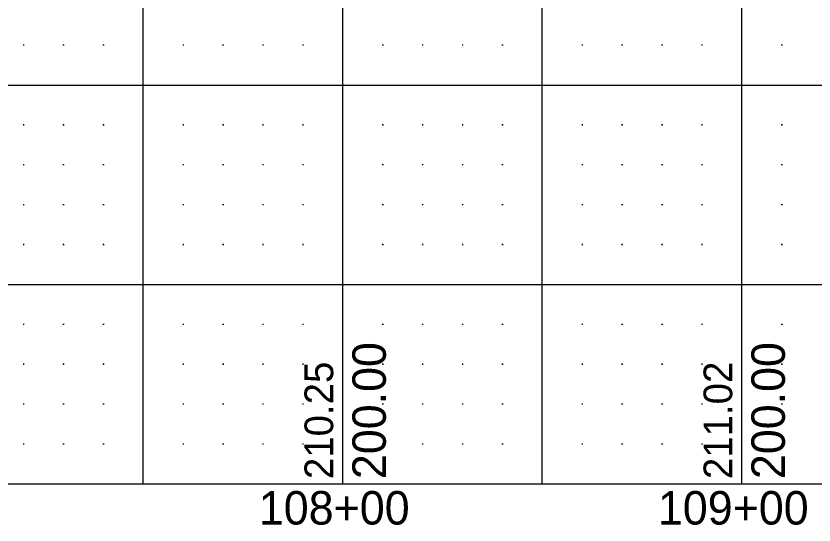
# Model space of a CAD drawing. Extents: x 471 to 2121, y 140 to 650.
# Drawn here: x 1354.2 to 1554.2, y 139.7 to 267.3 of the extents above; entities that cross this region are included whole.
import ezdxf

# ---------------------------------------------------------------- set-up
doc = ezdxf.new("R2010")
doc.units = 0
for name, color, linetype in [('DSN_DRFT_Border Grid', 7, 'Continuous'), ('DSN_RDWY_Prof Annotation', 7, 'Continuous'), ('EX_Profile Annotation', 7, 'Continuous')]:
    doc.layers.add(name, color=color, linetype=linetype)

msp = doc.modelspace()

# ---------------------------------------------------------------- linework, layer by layer
at = {"layer": 'DSN_DRFT_Border Grid'}
for p, q in [((1386.06, 150), (1386.06, 650)), ((1386.06, 150), (1386.06, 650)), ((1436.06, 150), (1436.06, 650)), ((1436.06, 150), (1436.06, 650)), ((1486.06, 150), (1486.06, 650)), ((1486.06, 150), (1486.06, 650)), ((1536.06, 150), (1536.06, 650)), ((1536.06, 150), (1536.06, 650)), ((1356.06, 260.12), (1356.06, 259.88)), ((1356.06, 260.12), (1356.06, 259.88)), ((1366.06, 260.12), (1366.06, 259.88)), ((1366.06, 260.12), (1366.06, 259.88)), ((1376.06, 260.12), (1376.06, 259.88)), ((1376.06, 260.12), (1376.06, 259.88)), ((1396.06, 260.12), (1396.06, 259.88)), ((1396.06, 260.12), (1396.06, 259.88)), ((1406.06, 260.12), (1406.06, 259.88)), ((1406.06, 260.12), (1406.06, 259.88)), ((1416.06, 260.12), (1416.06, 259.88)), ((1416.06, 260.12), (1416.06, 259.88)), ((1426.06, 260.12), (1426.06, 259.88)), ((1426.06, 260.12), (1426.06, 259.88)), ((1446.06, 260.12), (1446.06, 259.88)), ((1446.06, 260.12), (1446.06, 259.88)), ((1456.06, 260.12), (1456.06, 259.88)), ((1456.06, 260.12), (1456.06, 259.88)), ((1466.06, 260.12), (1466.06, 259.88)), ((1466.06, 260.12), (1466.06, 259.88)), ((1476.06, 260.12), (1476.06, 259.88)), ((1476.06, 260.12), (1476.06, 259.88)), ((1496.06, 260.12), (1496.06, 259.88)), ((1496.06, 260.12), (1496.06, 259.88)), ((1506.06, 260.12), (1506.06, 259.88)), ((1506.06, 260.12), (1506.06, 259.88)), ((1516.06, 260.12), (1516.06, 259.88)), ((1516.06, 260.12), (1516.06, 259.88)), ((1526.06, 260.12), (1526.06, 259.88)), ((1526.06, 260.12), (1526.06, 259.88)), ((1546.06, 260.12), (1546.06, 259.88)), ((1546.06, 260.12), (1546.06, 259.88)), ((1356.18, 260), (1355.94, 260)), ((1356.18, 260), (1355.94, 260)), ((1366.18, 260), (1365.94, 260)), ((1366.18, 260), (1365.94, 260)), ((1376.18, 260), (1375.94, 260)), ((1376.18, 260), (1375.94, 260)), ((1396.18, 260), (1395.94, 260)), ((1396.18, 260), (1395.94, 260)), ((1406.18, 260), (1405.94, 260)), ((1406.18, 260), (1405.94, 260)), ((1416.18, 260), (1415.94, 260)), ((1416.18, 260), (1415.94, 260)), ((1426.18, 260), (1425.94, 260)), ((1426.18, 260), (1425.94, 260)), ((1446.18, 260), (1445.94, 260)), ((1446.18, 260), (1445.94, 260)), ((1456.18, 260), (1455.94, 260)), ((1456.18, 260), (1455.94, 260)), ((1466.18, 260), (1465.94, 260)), ((1466.18, 260), (1465.94, 260)), ((1476.18, 260), (1475.94, 260)), ((1476.18, 260), (1475.94, 260)), ((1496.18, 260), (1495.94, 260)), ((1496.18, 260), (1495.94, 260)), ((1506.18, 260), (1505.94, 260)), ((1506.18, 260), (1505.94, 260)), ((1516.18, 260), (1515.94, 260)), ((1516.18, 260), (1515.94, 260)), ((1526.18, 260), (1525.94, 260)), ((1526.18, 260), (1525.94, 260)), ((1546.18, 260), (1545.94, 260)), ((1546.18, 260), (1545.94, 260)), ((521.06, 250), (2071.06, 250)), ((521.06, 250), (2071.06, 250)), ((1356.06, 240.12), (1356.06, 239.88)), ((1356.06, 240.12), (1356.06, 239.88)), ((1366.06, 240.12), (1366.06, 239.88)), ((1366.06, 240.12), (1366.06, 239.88)), ((1376.06, 240.12), (1376.06, 239.88)), ((1376.06, 240.12), (1376.06, 239.88)), ((1396.06, 240.12), (1396.06, 239.88)), ((1396.06, 240.12), (1396.06, 239.88)), ((1406.06, 240.12), (1406.06, 239.88)), ((1406.06, 240.12), (1406.06, 239.88)), ((1416.06, 240.12), (1416.06, 239.88)), ((1416.06, 240.12), (1416.06, 239.88)), ((1426.06, 240.12), (1426.06, 239.88)), ((1426.06, 240.12), (1426.06, 239.88)), ((1446.06, 240.12), (1446.06, 239.88)), ((1446.06, 240.12), (1446.06, 239.88)), ((1456.06, 240.12), (1456.06, 239.88)), ((1456.06, 240.12), (1456.06, 239.88)), ((1466.06, 240.12), (1466.06, 239.88)), ((1466.06, 240.12), (1466.06, 239.88)), ((1476.06, 240.12), (1476.06, 239.88)), ((1476.06, 240.12), (1476.06, 239.88)), ((1496.06, 240.12), (1496.06, 239.88)), ((1496.06, 240.12), (1496.06, 239.88)), ((1506.06, 240.12), (1506.06, 239.88)), ((1506.06, 240.12), (1506.06, 239.88)), ((1516.06, 240.12), (1516.06, 239.88)), ((1516.06, 240.12), (1516.06, 239.88)), ((1526.06, 240.12), (1526.06, 239.88)), ((1526.06, 240.12), (1526.06, 239.88)), ((1546.06, 240.12), (1546.06, 239.88)), ((1546.06, 240.12), (1546.06, 239.88)), ((1356.18, 240), (1355.94, 240)), ((1356.18, 240), (1355.94, 240)), ((1366.18, 240), (1365.94, 240)), ((1366.18, 240), (1365.94, 240)), ((1376.18, 240), (1375.94, 240)), ((1376.18, 240), (1375.94, 240)), ((1396.18, 240), (1395.94, 240)), ((1396.18, 240), (1395.94, 240)), ((1406.18, 240), (1405.94, 240)), ((1406.18, 240), (1405.94, 240)), ((1416.18, 240), (1415.94, 240)), ((1416.18, 240), (1415.94, 240)), ((1426.18, 240), (1425.94, 240)), ((1426.18, 240), (1425.94, 240)), ((1446.18, 240), (1445.94, 240)), ((1446.18, 240), (1445.94, 240)), ((1456.18, 240), (1455.94, 240)), ((1456.18, 240), (1455.94, 240)), ((1466.18, 240), (1465.94, 240)), ((1466.18, 240), (1465.94, 240)), ((1476.18, 240), (1475.94, 240)), ((1476.18, 240), (1475.94, 240)), ((1496.18, 240), (1495.94, 240)), ((1496.18, 240), (1495.94, 240)), ((1506.18, 240), (1505.94, 240)), ((1506.18, 240), (1505.94, 240)), ((1516.18, 240), (1515.94, 240)), ((1516.18, 240), (1515.94, 240)), ((1526.18, 240), (1525.94, 240)), ((1526.18, 240), (1525.94, 240)), ((1546.18, 240), (1545.94, 240)), ((1546.18, 240), (1545.94, 240)), ((1356.06, 230.12), (1356.06, 229.88)), ((1356.06, 230.12), (1356.06, 229.88)), ((1366.06, 230.12), (1366.06, 229.88)), ((1366.06, 230.12), (1366.06, 229.88)), ((1376.06, 230.12), (1376.06, 229.88)), ((1376.06, 230.12), (1376.06, 229.88)), ((1396.06, 230.12), (1396.06, 229.88)), ((1396.06, 230.12), (1396.06, 229.88)), ((1406.06, 230.12), (1406.06, 229.88)), ((1406.06, 230.12), (1406.06, 229.88)), ((1416.06, 230.12), (1416.06, 229.88)), ((1416.06, 230.12), (1416.06, 229.88)), ((1426.06, 230.12), (1426.06, 229.88)), ((1426.06, 230.12), (1426.06, 229.88)), ((1446.06, 230.12), (1446.06, 229.88)), ((1446.06, 230.12), (1446.06, 229.88)), ((1456.06, 230.12), (1456.06, 229.88)), ((1456.06, 230.12), (1456.06, 229.88)), ((1466.06, 230.12), (1466.06, 229.88)), ((1466.06, 230.12), (1466.06, 229.88)), ((1476.06, 230.12), (1476.06, 229.88)), ((1476.06, 230.12), (1476.06, 229.88)), ((1496.06, 230.12), (1496.06, 229.88)), ((1496.06, 230.12), (1496.06, 229.88)), ((1506.06, 230.12), (1506.06, 229.88)), ((1506.06, 230.12), (1506.06, 229.88)), ((1516.06, 230.12), (1516.06, 229.88)), ((1516.06, 230.12), (1516.06, 229.88)), ((1526.06, 230.12), (1526.06, 229.88)), ((1526.06, 230.12), (1526.06, 229.88)), ((1546.06, 230.12), (1546.06, 229.88)), ((1546.06, 230.12), (1546.06, 229.88)), ((1356.18, 230), (1355.94, 230)), ((1356.18, 230), (1355.94, 230)), ((1366.18, 230), (1365.94, 230)), ((1366.18, 230), (1365.94, 230)), ((1376.18, 230), (1375.94, 230)), ((1376.18, 230), (1375.94, 230)), ((1396.18, 230), (1395.94, 230)), ((1396.18, 230), (1395.94, 230)), ((1406.18, 230), (1405.94, 230)), ((1406.18, 230), (1405.94, 230)), ((1416.18, 230), (1415.94, 230)), ((1416.18, 230), (1415.94, 230)), ((1426.18, 230), (1425.94, 230)), ((1426.18, 230), (1425.94, 230)), ((1446.18, 230), (1445.94, 230)), ((1446.18, 230), (1445.94, 230)), ((1456.18, 230), (1455.94, 230)), ((1456.18, 230), (1455.94, 230)), ((1466.18, 230), (1465.94, 230)), ((1466.18, 230), (1465.94, 230)), ((1476.18, 230), (1475.94, 230)), ((1476.18, 230), (1475.94, 230)), ((1496.18, 230), (1495.94, 230)), ((1496.18, 230), (1495.94, 230)), ((1506.18, 230), (1505.94, 230)), ((1506.18, 230), (1505.94, 230)), ((1516.18, 230), (1515.94, 230)), ((1516.18, 230), (1515.94, 230)), ((1526.18, 230), (1525.94, 230)), ((1526.18, 230), (1525.94, 230)), ((1546.18, 230), (1545.94, 230)), ((1546.18, 230), (1545.94, 230)), ((1356.06, 220.12), (1356.06, 219.88)), ((1356.06, 220.12), (1356.06, 219.88)), ((1366.06, 220.12), (1366.06, 219.88)), ((1366.06, 220.12), (1366.06, 219.88)), ((1376.06, 220.12), (1376.06, 219.88)), ((1376.06, 220.12), (1376.06, 219.88)), ((1396.06, 220.12), (1396.06, 219.88)), ((1396.06, 220.12), (1396.06, 219.88)), ((1406.06, 220.12), (1406.06, 219.88)), ((1406.06, 220.12), (1406.06, 219.88)), ((1416.06, 220.12), (1416.06, 219.88)), ((1416.06, 220.12), (1416.06, 219.88)), ((1426.06, 220.12), (1426.06, 219.88)), ((1426.06, 220.12), (1426.06, 219.88)), ((1446.06, 220.12), (1446.06, 219.88)), ((1446.06, 220.12), (1446.06, 219.88)), ((1456.06, 220.12), (1456.06, 219.88)), ((1456.06, 220.12), (1456.06, 219.88)), ((1466.06, 220.12), (1466.06, 219.88)), ((1466.06, 220.12), (1466.06, 219.88)), ((1476.06, 220.12), (1476.06, 219.88)), ((1476.06, 220.12), (1476.06, 219.88)), ((1496.06, 220.12), (1496.06, 219.88)), ((1496.06, 220.12), (1496.06, 219.88)), ((1506.06, 220.12), (1506.06, 219.88)), ((1506.06, 220.12), (1506.06, 219.88)), ((1516.06, 220.12), (1516.06, 219.88)), ((1516.06, 220.12), (1516.06, 219.88)), ((1526.06, 220.12), (1526.06, 219.88)), ((1526.06, 220.12), (1526.06, 219.88)), ((1546.06, 220.12), (1546.06, 219.88)), ((1546.06, 220.12), (1546.06, 219.88)), ((1356.18, 220), (1355.94, 220)), ((1356.18, 220), (1355.94, 220)), ((1366.18, 220), (1365.94, 220)), ((1366.18, 220), (1365.94, 220)), ((1376.18, 220), (1375.94, 220)), ((1376.18, 220), (1375.94, 220)), ((1396.18, 220), (1395.94, 220)), ((1396.18, 220), (1395.94, 220)), ((1406.18, 220), (1405.94, 220)), ((1406.18, 220), (1405.94, 220)), ((1416.18, 220), (1415.94, 220)), ((1416.18, 220), (1415.94, 220)), ((1426.18, 220), (1425.94, 220)), ((1426.18, 220), (1425.94, 220)), ((1446.18, 220), (1445.94, 220)), ((1446.18, 220), (1445.94, 220)), ((1456.18, 220), (1455.94, 220)), ((1456.18, 220), (1455.94, 220)), ((1466.18, 220), (1465.94, 220)), ((1466.18, 220), (1465.94, 220)), ((1476.18, 220), (1475.94, 220)), ((1476.18, 220), (1475.94, 220)), ((1496.18, 220), (1495.94, 220)), ((1496.18, 220), (1495.94, 220)), ((1506.18, 220), (1505.94, 220)), ((1506.18, 220), (1505.94, 220)), ((1516.18, 220), (1515.94, 220)), ((1516.18, 220), (1515.94, 220)), ((1526.18, 220), (1525.94, 220)), ((1526.18, 220), (1525.94, 220)), ((1546.18, 220), (1545.94, 220)), ((1546.18, 220), (1545.94, 220)), ((1356.06, 210.12), (1356.06, 209.88)), ((1356.06, 210.12), (1356.06, 209.88)), ((1366.06, 210.12), (1366.06, 209.88)), ((1366.06, 210.12), (1366.06, 209.88)), ((1376.06, 210.12), (1376.06, 209.88)), ((1376.06, 210.12), (1376.06, 209.88)), ((1396.06, 210.12), (1396.06, 209.88)), ((1396.06, 210.12), (1396.06, 209.88)), ((1406.06, 210.12), (1406.06, 209.88)), ((1406.06, 210.12), (1406.06, 209.88)), ((1416.06, 210.12), (1416.06, 209.88)), ((1416.06, 210.12), (1416.06, 209.88)), ((1426.06, 210.12), (1426.06, 209.88)), ((1426.06, 210.12), (1426.06, 209.88)), ((1446.06, 210.12), (1446.06, 209.88)), ((1446.06, 210.12), (1446.06, 209.88)), ((1456.06, 210.12), (1456.06, 209.88)), ((1456.06, 210.12), (1456.06, 209.88)), ((1466.06, 210.12), (1466.06, 209.88)), ((1466.06, 210.12), (1466.06, 209.88)), ((1476.06, 210.12), (1476.06, 209.88)), ((1476.06, 210.12), (1476.06, 209.88)), ((1496.06, 210.12), (1496.06, 209.88)), ((1496.06, 210.12), (1496.06, 209.88)), ((1506.06, 210.12), (1506.06, 209.88)), ((1506.06, 210.12), (1506.06, 209.88)), ((1516.06, 210.12), (1516.06, 209.88)), ((1516.06, 210.12), (1516.06, 209.88)), ((1526.06, 210.12), (1526.06, 209.88)), ((1526.06, 210.12), (1526.06, 209.88)), ((1546.06, 210.12), (1546.06, 209.88)), ((1546.06, 210.12), (1546.06, 209.88)), ((1356.18, 210), (1355.94, 210)), ((1356.18, 210), (1355.94, 210)), ((1366.18, 210), (1365.94, 210)), ((1366.18, 210), (1365.94, 210)), ((1376.18, 210), (1375.94, 210)), ((1376.18, 210), (1375.94, 210)), ((1396.18, 210), (1395.94, 210)), ((1396.18, 210), (1395.94, 210)), ((1406.18, 210), (1405.94, 210)), ((1406.18, 210), (1405.94, 210)), ((1416.18, 210), (1415.94, 210)), ((1416.18, 210), (1415.94, 210)), ((1426.18, 210), (1425.94, 210)), ((1426.18, 210), (1425.94, 210)), ((1446.18, 210), (1445.94, 210)), ((1446.18, 210), (1445.94, 210)), ((1456.18, 210), (1455.94, 210)), ((1456.18, 210), (1455.94, 210)), ((1466.18, 210), (1465.94, 210)), ((1466.18, 210), (1465.94, 210)), ((1476.18, 210), (1475.94, 210)), ((1476.18, 210), (1475.94, 210)), ((1496.18, 210), (1495.94, 210)), ((1496.18, 210), (1495.94, 210)), ((1506.18, 210), (1505.94, 210)), ((1506.18, 210), (1505.94, 210)), ((1516.18, 210), (1515.94, 210)), ((1516.18, 210), (1515.94, 210)), ((1526.18, 210), (1525.94, 210)), ((1526.18, 210), (1525.94, 210)), ((1546.18, 210), (1545.94, 210)), ((1546.18, 210), (1545.94, 210)), ((521.06, 200), (2071.06, 200)), ((521.06, 200), (2071.06, 200)), ((1356.06, 190.12), (1356.06, 189.88)), ((1356.06, 190.12), (1356.06, 189.88)), ((1366.06, 190.12), (1366.06, 189.88)), ((1366.06, 190.12), (1366.06, 189.88)), ((1376.06, 190.12), (1376.06, 189.88)), ((1376.06, 190.12), (1376.06, 189.88)), ((1396.06, 190.12), (1396.06, 189.88)), ((1396.06, 190.12), (1396.06, 189.88)), ((1406.06, 190.12), (1406.06, 189.88)), ((1406.06, 190.12), (1406.06, 189.88)), ((1416.06, 190.12), (1416.06, 189.88)), ((1416.06, 190.12), (1416.06, 189.88)), ((1426.06, 190.12), (1426.06, 189.88)), ((1426.06, 190.12), (1426.06, 189.88)), ((1446.06, 190.12), (1446.06, 189.88)), ((1446.06, 190.12), (1446.06, 189.88)), ((1456.06, 190.12), (1456.06, 189.88)), ((1456.06, 190.12), (1456.06, 189.88)), ((1466.06, 190.12), (1466.06, 189.88)), ((1466.06, 190.12), (1466.06, 189.88)), ((1476.06, 190.12), (1476.06, 189.88)), ((1476.06, 190.12), (1476.06, 189.88)), ((1496.06, 190.12), (1496.06, 189.88)), ((1496.06, 190.12), (1496.06, 189.88)), ((1506.06, 190.12), (1506.06, 189.88)), ((1506.06, 190.12), (1506.06, 189.88)), ((1516.06, 190.12), (1516.06, 189.88)), ((1516.06, 190.12), (1516.06, 189.88)), ((1526.06, 190.12), (1526.06, 189.88)), ((1526.06, 190.12), (1526.06, 189.88)), ((1546.06, 190.12), (1546.06, 189.88)), ((1546.06, 190.12), (1546.06, 189.88)), ((1356.18, 190), (1355.94, 190)), ((1356.18, 190), (1355.94, 190)), ((1366.18, 190), (1365.94, 190)), ((1366.18, 190), (1365.94, 190)), ((1376.18, 190), (1375.94, 190)), ((1376.18, 190), (1375.94, 190)), ((1396.18, 190), (1395.94, 190)), ((1396.18, 190), (1395.94, 190)), ((1406.18, 190), (1405.94, 190)), ((1406.18, 190), (1405.94, 190)), ((1416.18, 190), (1415.94, 190)), ((1416.18, 190), (1415.94, 190)), ((1426.18, 190), (1425.94, 190)), ((1426.18, 190), (1425.94, 190)), ((1446.18, 190), (1445.94, 190)), ((1446.18, 190), (1445.94, 190)), ((1456.18, 190), (1455.94, 190)), ((1456.18, 190), (1455.94, 190)), ((1466.18, 190), (1465.94, 190)), ((1466.18, 190), (1465.94, 190)), ((1476.18, 190), (1475.94, 190)), ((1476.18, 190), (1475.94, 190)), ((1496.18, 190), (1495.94, 190)), ((1496.18, 190), (1495.94, 190)), ((1506.18, 190), (1505.94, 190)), ((1506.18, 190), (1505.94, 190)), ((1516.18, 190), (1515.94, 190)), ((1516.18, 190), (1515.94, 190)), ((1526.18, 190), (1525.94, 190)), ((1526.18, 190), (1525.94, 190)), ((1546.18, 190), (1545.94, 190)), ((1546.18, 190), (1545.94, 190)), ((1356.06, 180.12), (1356.06, 179.88)), ((1356.06, 180.12), (1356.06, 179.88)), ((1366.06, 180.12), (1366.06, 179.88)), ((1366.06, 180.12), (1366.06, 179.88)), ((1376.06, 180.12), (1376.06, 179.88)), ((1376.06, 180.12), (1376.06, 179.88)), ((1396.06, 180.12), (1396.06, 179.88)), ((1396.06, 180.12), (1396.06, 179.88)), ((1406.06, 180.12), (1406.06, 179.88)), ((1406.06, 180.12), (1406.06, 179.88)), ((1416.06, 180.12), (1416.06, 179.88)), ((1416.06, 180.12), (1416.06, 179.88)), ((1426.06, 180.12), (1426.06, 179.88)), ((1426.06, 180.12), (1426.06, 179.88)), ((1446.06, 180.12), (1446.06, 179.88)), ((1446.06, 180.12), (1446.06, 179.88)), ((1456.06, 180.12), (1456.06, 179.88)), ((1456.06, 180.12), (1456.06, 179.88)), ((1466.06, 180.12), (1466.06, 179.88)), ((1466.06, 180.12), (1466.06, 179.88)), ((1476.06, 180.12), (1476.06, 179.88)), ((1476.06, 180.12), (1476.06, 179.88)), ((1496.06, 180.12), (1496.06, 179.88)), ((1496.06, 180.12), (1496.06, 179.88)), ((1506.06, 180.12), (1506.06, 179.88)), ((1506.06, 180.12), (1506.06, 179.88)), ((1516.06, 180.12), (1516.06, 179.88)), ((1516.06, 180.12), (1516.06, 179.88)), ((1526.06, 180.12), (1526.06, 179.88)), ((1526.06, 180.12), (1526.06, 179.88)), ((1546.06, 180.12), (1546.06, 179.88)), ((1546.06, 180.12), (1546.06, 179.88)), ((1356.18, 180), (1355.94, 180)), ((1356.18, 180), (1355.94, 180)), ((1366.18, 180), (1365.94, 180)), ((1366.18, 180), (1365.94, 180)), ((1376.18, 180), (1375.94, 180)), ((1376.18, 180), (1375.94, 180)), ((1396.18, 180), (1395.94, 180)), ((1396.18, 180), (1395.94, 180)), ((1406.18, 180), (1405.94, 180)), ((1406.18, 180), (1405.94, 180)), ((1416.18, 180), (1415.94, 180)), ((1416.18, 180), (1415.94, 180)), ((1426.18, 180), (1425.94, 180)), ((1426.18, 180), (1425.94, 180)), ((1446.18, 180), (1445.94, 180)), ((1446.18, 180), (1445.94, 180)), ((1456.18, 180), (1455.94, 180)), ((1456.18, 180), (1455.94, 180)), ((1466.18, 180), (1465.94, 180)), ((1466.18, 180), (1465.94, 180)), ((1476.18, 180), (1475.94, 180)), ((1476.18, 180), (1475.94, 180)), ((1496.18, 180), (1495.94, 180)), ((1496.18, 180), (1495.94, 180)), ((1506.18, 180), (1505.94, 180)), ((1506.18, 180), (1505.94, 180)), ((1516.18, 180), (1515.94, 180)), ((1516.18, 180), (1515.94, 180)), ((1526.18, 180), (1525.94, 180)), ((1526.18, 180), (1525.94, 180)), ((1546.18, 180), (1545.94, 180)), ((1546.18, 180), (1545.94, 180)), ((1356.06, 170.12), (1356.06, 169.88)), ((1356.06, 170.12), (1356.06, 169.88)), ((1366.06, 170.12), (1366.06, 169.88)), ((1366.06, 170.12), (1366.06, 169.88)), ((1376.06, 170.12), (1376.06, 169.88)), ((1376.06, 170.12), (1376.06, 169.88)), ((1396.06, 170.12), (1396.06, 169.88)), ((1396.06, 170.12), (1396.06, 169.88)), ((1406.06, 170.12), (1406.06, 169.88)), ((1406.06, 170.12), (1406.06, 169.88)), ((1416.06, 170.12), (1416.06, 169.88)), ((1416.06, 170.12), (1416.06, 169.88)), ((1426.06, 170.12), (1426.06, 169.88)), ((1426.06, 170.12), (1426.06, 169.88)), ((1446.06, 170.12), (1446.06, 169.88)), ((1446.06, 170.12), (1446.06, 169.88)), ((1456.06, 170.12), (1456.06, 169.88)), ((1456.06, 170.12), (1456.06, 169.88)), ((1466.06, 170.12), (1466.06, 169.88)), ((1466.06, 170.12), (1466.06, 169.88)), ((1476.06, 170.12), (1476.06, 169.88)), ((1476.06, 170.12), (1476.06, 169.88)), ((1496.06, 170.12), (1496.06, 169.88)), ((1496.06, 170.12), (1496.06, 169.88)), ((1506.06, 170.12), (1506.06, 169.88)), ((1506.06, 170.12), (1506.06, 169.88)), ((1516.06, 170.12), (1516.06, 169.88)), ((1516.06, 170.12), (1516.06, 169.88)), ((1526.06, 170.12), (1526.06, 169.88)), ((1526.06, 170.12), (1526.06, 169.88)), ((1546.06, 170.12), (1546.06, 169.88)), ((1546.06, 170.12), (1546.06, 169.88)), ((1356.18, 170), (1355.94, 170)), ((1356.18, 170), (1355.94, 170)), ((1366.18, 170), (1365.94, 170)), ((1366.18, 170), (1365.94, 170)), ((1376.18, 170), (1375.94, 170)), ((1376.18, 170), (1375.94, 170)), ((1396.18, 170), (1395.94, 170)), ((1396.18, 170), (1395.94, 170)), ((1406.18, 170), (1405.94, 170)), ((1406.18, 170), (1405.94, 170)), ((1416.18, 170), (1415.94, 170)), ((1416.18, 170), (1415.94, 170)), ((1426.18, 170), (1425.94, 170)), ((1426.18, 170), (1425.94, 170)), ((1446.18, 170), (1445.94, 170)), ((1446.18, 170), (1445.94, 170)), ((1456.18, 170), (1455.94, 170)), ((1456.18, 170), (1455.94, 170)), ((1466.18, 170), (1465.94, 170)), ((1466.18, 170), (1465.94, 170)), ((1476.18, 170), (1475.94, 170)), ((1476.18, 170), (1475.94, 170)), ((1496.18, 170), (1495.94, 170)), ((1496.18, 170), (1495.94, 170)), ((1506.18, 170), (1505.94, 170)), ((1506.18, 170), (1505.94, 170)), ((1516.18, 170), (1515.94, 170)), ((1516.18, 170), (1515.94, 170)), ((1526.18, 170), (1525.94, 170)), ((1526.18, 170), (1525.94, 170)), ((1546.18, 170), (1545.94, 170)), ((1546.18, 170), (1545.94, 170)), ((1356.06, 160.12), (1356.06, 159.88)), ((1356.06, 160.12), (1356.06, 159.88)), ((1366.06, 160.12), (1366.06, 159.88)), ((1366.06, 160.12), (1366.06, 159.88)), ((1376.06, 160.12), (1376.06, 159.88)), ((1376.06, 160.12), (1376.06, 159.88)), ((1396.06, 160.12), (1396.06, 159.88)), ((1396.06, 160.12), (1396.06, 159.88)), ((1406.06, 160.12), (1406.06, 159.88)), ((1406.06, 160.12), (1406.06, 159.88)), ((1416.06, 160.12), (1416.06, 159.88)), ((1416.06, 160.12), (1416.06, 159.88)), ((1426.06, 160.12), (1426.06, 159.88)), ((1426.06, 160.12), (1426.06, 159.88)), ((1446.06, 160.12), (1446.06, 159.88)), ((1446.06, 160.12), (1446.06, 159.88)), ((1456.06, 160.12), (1456.06, 159.88)), ((1456.06, 160.12), (1456.06, 159.88)), ((1466.06, 160.12), (1466.06, 159.88)), ((1466.06, 160.12), (1466.06, 159.88)), ((1476.06, 160.12), (1476.06, 159.88)), ((1476.06, 160.12), (1476.06, 159.88)), ((1496.06, 160.12), (1496.06, 159.88)), ((1496.06, 160.12), (1496.06, 159.88)), ((1506.06, 160.12), (1506.06, 159.88)), ((1506.06, 160.12), (1506.06, 159.88)), ((1516.06, 160.12), (1516.06, 159.88)), ((1516.06, 160.12), (1516.06, 159.88)), ((1526.06, 160.12), (1526.06, 159.88)), ((1526.06, 160.12), (1526.06, 159.88)), ((1546.06, 160.12), (1546.06, 159.88)), ((1546.06, 160.12), (1546.06, 159.88)), ((1356.18, 160), (1355.94, 160)), ((1356.18, 160), (1355.94, 160)), ((1366.18, 160), (1365.94, 160)), ((1366.18, 160), (1365.94, 160)), ((1376.18, 160), (1375.94, 160)), ((1376.18, 160), (1375.94, 160)), ((1396.18, 160), (1395.94, 160)), ((1396.18, 160), (1395.94, 160)), ((1406.18, 160), (1405.94, 160)), ((1406.18, 160), (1405.94, 160)), ((1416.18, 160), (1415.94, 160)), ((1416.18, 160), (1415.94, 160)), ((1426.18, 160), (1425.94, 160)), ((1426.18, 160), (1425.94, 160)), ((1446.18, 160), (1445.94, 160)), ((1446.18, 160), (1445.94, 160)), ((1456.18, 160), (1455.94, 160)), ((1456.18, 160), (1455.94, 160)), ((1466.18, 160), (1465.94, 160)), ((1466.18, 160), (1465.94, 160)), ((1476.18, 160), (1475.94, 160)), ((1476.18, 160), (1475.94, 160)), ((1496.18, 160), (1495.94, 160)), ((1496.18, 160), (1495.94, 160)), ((1506.18, 160), (1505.94, 160)), ((1506.18, 160), (1505.94, 160)), ((1516.18, 160), (1515.94, 160)), ((1516.18, 160), (1515.94, 160)), ((1526.18, 160), (1525.94, 160)), ((1526.18, 160), (1525.94, 160)), ((1546.18, 160), (1545.94, 160)), ((1546.18, 160), (1545.94, 160)), ((521.06, 150), (2071.06, 150)), ((521.06, 150), (2071.06, 150))]:
    msp.add_line(p, q, dxfattribs=at)

# ---------------------------------------------------------------- texts
at = {"layer": 'DSN_RDWY_Prof Annotation'}
for p in [(1446.86, 151.2), (1546.86, 151.2)]:
    msp.add_text('200.00', height=8.4, rotation=90, dxfattribs=at).set_placement(p)
for s, p in [('108+00', (1415.02, 139.8)), ('108+00', (1415.02, 139.8)), ('109+00', (1515.02, 139.8)), ('109+00', (1515.02, 139.8))]:
    msp.add_text(s, height=8.4, dxfattribs=at).set_placement(p)
at = {"layer": 'EX_Profile Annotation'}
for s, p in [('210.25', (1433.66, 151.2)), ('211.02', (1533.67, 151.2))]:
    msp.add_text(s, height=7.2, rotation=90, dxfattribs=at).set_placement(p)

doc.saveas('drawing.dxf')
